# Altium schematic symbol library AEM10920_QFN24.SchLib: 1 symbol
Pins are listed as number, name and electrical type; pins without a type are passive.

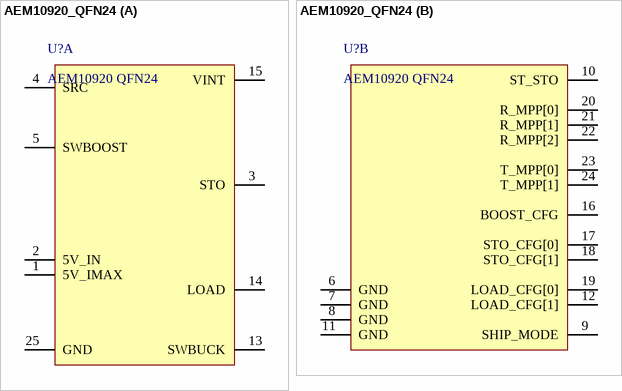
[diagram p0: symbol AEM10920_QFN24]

## AEM10920_QFN24
designator U?, comment AEM10920 QFN24
footprint QFN24_4x4mm_PITCH_0.5mm_PAD_2.7mm_QP235-00052 (QFN, 24-Leads, Body 4.00x4.00mm, Pitch 0.50mm, Thermal Pad 2.70x2.70mm, IPC High Density)
part A pins: 1 5V_IMAX, 2 5V_IN, 3 STO, 4 SRC, 5 SWBOOST, 13 SWBUCK, 14 LOAD, 15 VINT, 25 GND
part B pins: 6 GND, 7 GND, 8 GND, 9 SHIP_MODE, 10 ST_STO, 11 GND, 12 LOAD_CFG[1], 16 BOOST_CFG, 17 STO_CFG[0], 18 STO_CFG[1], 19 LOAD_CFG[0], 20 R_MPP[0], 21 R_MPP[1], 22 R_MPP[2], 23 T_MPP[0], 24 T_MPP[1]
